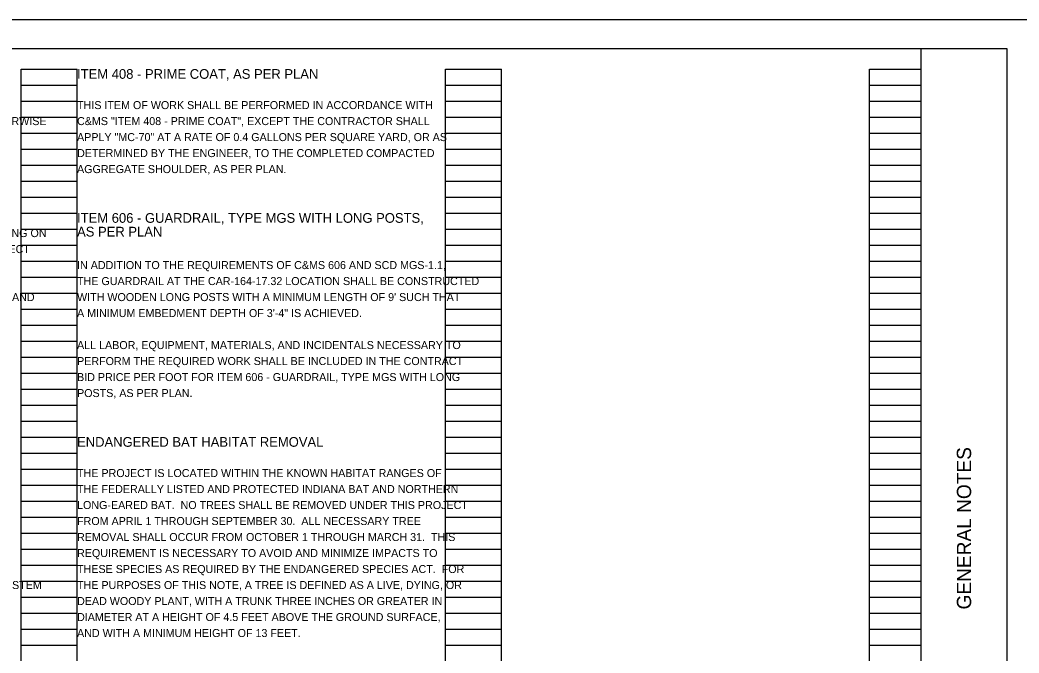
# Model space of a CAD drawing. Extents: x -6.7 to 44.8, y 0 to 42.6.
# Drawn here: x 16.24 to 33.71, y 10.92 to 22 of the extents above; entities that cross this region are included whole.
import ezdxf

# ---------------------------------------------------------------- set-up
doc = ezdxf.new("R2010")
doc.units = 0
for name, color, linetype in [('SH_Border', 7, 'Continuous'), ('SH_Cut_Line', 7, 'Continuous'), ('SH_Data', 7, 'Continuous'), ('SH_Text', 7, 'Continuous')]:
    doc.layers.add(name, color=color, linetype=linetype)

msp = doc.modelspace()

# ---------------------------------------------------------------- linework, layer by layer
at = {"layer": 'SH_Border'}
msp.add_line((32, 0.5), (32, 21.5), dxfattribs=at)
msp.add_lwpolyline([(1.5, 21.5), (33.5, 21.5), (33.5, 0.5), (1.5, 0.5)], close=True, dxfattribs=at)
at = {"layer": 'SH_Cut_Line'}
msp.add_lwpolyline([(0, 0), (34, 0), (34, 22), (0, 22)], close=True, dxfattribs=at)
at = {"layer": 'SH_Data'}
for p, q in [((16.26, 0.98), (16.26, 21.14)), ((16.26, 21.14), (17.24, 21.14)), ((17.24, 0.98), (17.24, 21.14)), ((23.68, 0.98), (23.68, 21.14)), ((23.68, 21.14), (24.66, 21.14)), ((24.66, 0.98), (24.66, 21.14)), ((31.1, 0.98), (31.1, 21.14)), ((31.1, 21.14), (32, 21.14)), ((32, 0.98), (32, 21.14)), ((16.26, 20.86), (17.24, 20.86)), ((23.68, 20.86), (24.66, 20.86)), ((31.1, 20.86), (32, 20.86)), ((16.26, 20.58), (17.24, 20.58)), ((23.68, 20.58), (24.66, 20.58)), ((31.1, 20.58), (32, 20.58)), ((16.26, 20.3), (17.24, 20.3)), ((23.68, 20.3), (24.66, 20.3)), ((31.1, 20.3), (32, 20.3)), ((16.26, 20.02), (17.24, 20.02)), ((23.68, 20.02), (24.66, 20.02)), ((31.1, 20.02), (32, 20.02)), ((16.26, 19.74), (17.24, 19.74)), ((23.68, 19.74), (24.66, 19.74)), ((31.1, 19.74), (32, 19.74)), ((16.26, 19.46), (17.24, 19.46)), ((23.68, 19.46), (24.66, 19.46)), ((31.1, 19.46), (32, 19.46)), ((16.26, 19.18), (17.24, 19.18)), ((23.68, 19.18), (24.66, 19.18)), ((31.1, 19.18), (32, 19.18)), ((16.26, 18.9), (17.24, 18.9)), ((23.68, 18.9), (24.66, 18.9)), ((31.1, 18.9), (32, 18.9)), ((16.26, 18.62), (17.24, 18.62)), ((23.68, 18.62), (24.66, 18.62)), ((31.1, 18.62), (32, 18.62)), ((16.26, 18.34), (17.24, 18.34)), ((23.68, 18.34), (24.66, 18.34)), ((31.1, 18.34), (32, 18.34)), ((16.26, 18.06), (17.24, 18.06)), ((23.68, 18.06), (24.66, 18.06)), ((31.1, 18.06), (32, 18.06)), ((16.26, 17.78), (17.24, 17.78)), ((23.68, 17.78), (24.66, 17.78)), ((31.1, 17.78), (32, 17.78)), ((16.26, 17.5), (17.24, 17.5)), ((23.68, 17.5), (24.66, 17.5)), ((31.1, 17.5), (32, 17.5)), ((16.26, 17.22), (17.24, 17.22)), ((23.68, 17.22), (24.66, 17.22)), ((31.1, 17.22), (32, 17.22)), ((16.26, 16.94), (17.24, 16.94)), ((23.68, 16.94), (24.66, 16.94)), ((31.1, 16.94), (32, 16.94)), ((16.26, 16.66), (17.24, 16.66)), ((23.68, 16.66), (24.66, 16.66)), ((31.1, 16.66), (32, 16.66)), ((16.26, 16.38), (17.24, 16.38)), ((23.68, 16.38), (24.66, 16.38)), ((31.1, 16.38), (32, 16.38)), ((16.26, 16.1), (17.24, 16.1)), ((23.68, 16.1), (24.66, 16.1)), ((31.1, 16.1), (32, 16.1)), ((16.26, 15.82), (17.24, 15.82)), ((23.68, 15.82), (24.66, 15.82)), ((31.1, 15.82), (32, 15.82)), ((16.26, 15.54), (17.24, 15.54)), ((23.68, 15.54), (24.66, 15.54)), ((31.1, 15.54), (32, 15.54)), ((16.26, 15.26), (17.24, 15.26)), ((23.68, 15.26), (24.66, 15.26)), ((31.1, 15.26), (32, 15.26)), ((16.26, 14.98), (17.24, 14.98)), ((23.68, 14.98), (24.66, 14.98)), ((31.1, 14.98), (32, 14.98)), ((16.26, 14.7), (17.24, 14.7)), ((23.68, 14.7), (24.66, 14.7)), ((31.1, 14.7), (32, 14.7)), ((16.26, 14.42), (17.24, 14.42)), ((23.68, 14.42), (24.66, 14.42)), ((31.1, 14.42), (32, 14.42)), ((16.26, 14.14), (17.24, 14.14)), ((23.68, 14.14), (24.66, 14.14)), ((31.1, 14.14), (32, 14.14)), ((16.26, 13.86), (17.24, 13.86)), ((23.68, 13.86), (24.66, 13.86)), ((31.1, 13.86), (32, 13.86)), ((16.26, 13.58), (17.24, 13.58)), ((23.68, 13.58), (24.66, 13.58)), ((31.1, 13.58), (32, 13.58)), ((16.26, 13.3), (17.24, 13.3)), ((23.68, 13.3), (24.66, 13.3)), ((31.1, 13.3), (32, 13.3)), ((16.26, 13.02), (17.24, 13.02)), ((23.68, 13.02), (24.66, 13.02)), ((31.1, 13.02), (32, 13.02)), ((16.26, 12.74), (17.24, 12.74)), ((23.68, 12.74), (24.66, 12.74)), ((31.1, 12.74), (32, 12.74)), ((16.26, 12.46), (17.24, 12.46)), ((23.68, 12.46), (24.66, 12.46)), ((31.1, 12.46), (32, 12.46)), ((16.26, 12.18), (17.24, 12.18)), ((23.68, 12.18), (24.66, 12.18)), ((31.1, 12.18), (32, 12.18)), ((16.26, 11.9), (17.24, 11.9)), ((23.68, 11.9), (24.66, 11.9)), ((31.1, 11.9), (32, 11.9)), ((16.26, 11.62), (17.24, 11.62)), ((23.68, 11.62), (24.66, 11.62)), ((31.1, 11.62), (32, 11.62)), ((16.26, 11.34), (17.24, 11.34)), ((23.68, 11.34), (24.66, 11.34)), ((31.1, 11.34), (32, 11.34)), ((16.26, 11.06), (17.24, 11.06)), ((23.68, 11.06), (24.66, 11.06)), ((31.1, 11.06), (32, 11.06))]:
    msp.add_line(p, q, dxfattribs=at)

# ---------------------------------------------------------------- texts
msp.add_text('GENERAL NOTES', height=0.25, rotation=90, dxfattribs=at).set_placement((32.875, 11.682))
at = {"layer": 'SH_Text'}
for s, height, p in [('ITEM 408 - PRIME COAT, AS PER PLAN', 0.17, (17.24, 20.97)), ('THIS ITEM OF WORK SHALL BE PERFORMED IN ACCORDANCE WITH ', 0.14, (17.24, 20.44)), ('SECTIONS APPLIES TO ALL CROSS-SECTIONS, EVEN THOUGH OTHERWISE ', 0.14, (9.82, 20.16)), ('C&MS "ITEM 408 - PRIME COAT", EXCEPT THE CONTRACTOR SHALL ', 0.14, (17.24, 20.16)), ('APPLY "MC-70" AT A RATE OF 0.4 GALLONS PER SQUARE YARD, OR AS ', 0.14, (17.24, 19.88)), ('DETERMINED BY THE ENGINEER, TO THE COMPLETED COMPACTED ', 0.14, (17.24, 19.6)), ('AGGREGATE SHOULDER, AS PER PLAN.', 0.14, (17.24, 19.32)), ('ITEM 606 - GUARDRAIL, TYPE MGS WITH LONG POSTS, ', 0.17, (17.24, 18.45)), ('AS PER PLAN', 0.17, (17.24, 18.21)), ('PRIMARY PROJECT CONTROL MONUMENTS GOVERN ALL POSITIONING ON ', 0.14, (9.82, 18.2)), ('ODOT PROJECTS. SEE THIS SHEET FOR TABLES CONTAINING PROJECT ', 0.14, (9.82, 17.92)), ('IN ADDITION TO THE REQUIREMENTS OF C&MS 606 AND SCD MGS-1.1, ', 0.14, (17.24, 17.64)), ('THE GUARDRAIL AT THE CAR-164-17.32 LOCATION SHALL BE CONSTRUCTED ', 0.14, (17.24, 17.36)), ('USE THE FOLLOWING PROJECT CONTROL, VERTICAL POSITIONING, AND ', 0.14, (9.82, 17.08)), ("WITH WOODEN LONG POSTS WITH A MINIMUM LENGTH OF 9' SUCH THAT ", 0.14, (17.24, 17.08)), ('A MINIMUM EMBEDMENT DEPTH OF 3\'-4" IS ACHIEVED.', 0.14, (17.24, 16.8)), ('ALL LABOR, EQUIPMENT, MATERIALS, AND INCIDENTALS NECESSARY TO ', 0.14, (17.24, 16.24)), ('PERFORM THE REQUIRED WORK SHALL BE INCLUDED IN THE CONTRACT ', 0.14, (17.24, 15.96)), ('BID PRICE PER FOOT FOR ITEM 606 - GUARDRAIL, TYPE MGS WITH LONG ', 0.14, (17.24, 15.68)), ('POSTS, AS PER PLAN.', 0.14, (17.24, 15.4)), ('ENDANGERED BAT HABITAT REMOVAL', 0.17, (17.24, 14.53)), ('THE PROJECT IS LOCATED WITHIN THE KNOWN HABITAT RANGES OF ', 0.14, (17.24, 14)), ('THE FEDERALLY LISTED AND PROTECTED INDIANA BAT AND NORTHERN ', 0.14, (17.24, 13.72)), ('LONG-EARED BAT.  NO TREES SHALL BE REMOVED UNDER THIS PROJECT ', 0.14, (17.24, 13.44)), ('FROM APRIL 1 THROUGH SEPTEMBER 30.  ALL NECESSARY TREE ', 0.14, (17.24, 13.16)), ('REMOVAL SHALL OCCUR FROM OCTOBER 1 THROUGH MARCH 31.  THIS ', 0.14, (17.24, 12.88)), ('REQUIREMENT IS NECESSARY TO AVOID AND MINIMIZE IMPACTS TO ', 0.14, (17.24, 12.6)), ('THESE SPECIES AS REQUIRED BY THE ENDANGERED SPECIES ACT.  FOR ', 0.14, (17.24, 12.32)), ('OHIO COUNTY COORDINATE SYSTEM ', 0.14, (13.18, 12.04)), ('THE PURPOSES OF THIS NOTE, A TREE IS DEFINED AS A LIVE, DYING, OR ', 0.14, (17.24, 12.04)), ('DEAD WOODY PLANT, WITH A TRUNK THREE INCHES OR GREATER IN ', 0.14, (17.24, 11.76)), ('DIAMETER AT A HEIGHT OF 4.5 FEET ABOVE THE GROUND SURFACE, ', 0.14, (17.24, 11.48)), ('AND WITH A MINIMUM HEIGHT OF 13 FEET.', 0.14, (17.24, 11.2))]:
    msp.add_text(s, height=height, dxfattribs=at).set_placement(p)

doc.saveas('drawing.dxf')
